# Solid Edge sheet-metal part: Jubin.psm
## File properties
Author: Egon 815
Template: Normal.psm
Last saved by: Egon 815
Revision: 1
Application: Solid Edge
Accuracy: 0,990
Material Thickness: 500,00 mm
Bend Radius: 1,00 mm
Relief Width: 1,00 mm
Relief Length: 0,00 mm
Neutral Factor: 0,330
Minimum Arc Length: 0,10 mm
Deviational Tolerance: 0,10 mm
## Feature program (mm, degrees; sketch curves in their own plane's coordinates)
base tab "unnamed BaseTab 1"
flange "Flange_1"
flange "Flange_2"
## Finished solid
Body 1: solid body, 14 faces, 36 edges, 24 vertices.
  Faces by surface: plane 10, cylinder 4
  Edges by curve: line 28, circle 8
Bounding box of the edges (mm): 1000.000 x 2000.000 x 1000.000, from (0, 0, 0) to (1000, 2000, 1000).
Cylindrical faces by radius (mm): R1 x2, R501 x2
Planar faces by outward normal: +x 1, +y 2, +z 3, -x 1, -y 2, -z 1
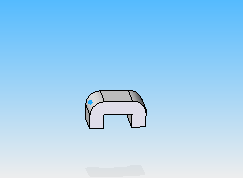
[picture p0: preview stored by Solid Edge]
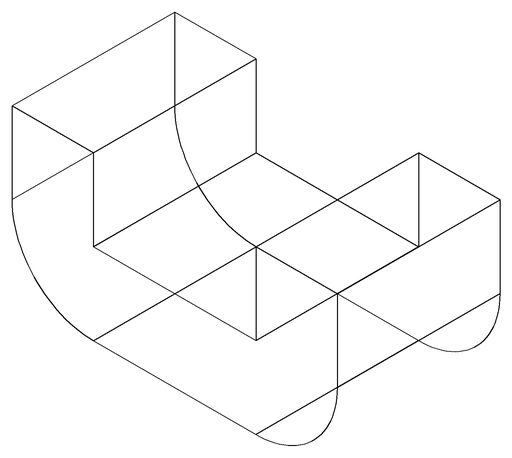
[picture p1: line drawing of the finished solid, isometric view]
